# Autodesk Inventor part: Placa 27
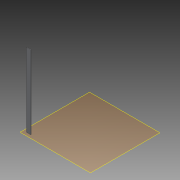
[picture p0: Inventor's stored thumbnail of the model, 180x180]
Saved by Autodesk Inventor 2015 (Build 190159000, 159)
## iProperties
Created: 2015-04
Part Number: Placa 27
Material: Generic
Document SubType Name: Modeling
Designer: suporte
Density: 1 g/cm^3
Appearance: Default
Author: suporte
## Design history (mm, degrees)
workplane "Work Plane1"
sketch "Sketch1"
  geometry: L1 (-900, -887.5)-(-800, -887.5) reference; L2 (-912.5, -900)-(-787.5, -900); L3 (-787.5, -900)-(-787.5, -887.5); L4 (-787.5, -887.5)-(-912.5, -887.5); L5 (-912.5, -887.5)-(-912.5, -900); 2 further points
  constraints: 8 end point, 2 midpoint, 2 parallel, 1 horizontal, 1 perpendicular
  dimensions: "d0" = 125 distance of L2.start L2.end; "d1" = 12.5 distance of L4.end L2.start
extrude "Extrusion1" new body sketch "Sketch1" distance "d2" = 2100; taper "d3" = 0 deg
body "Solid1"
node "Reference1"
